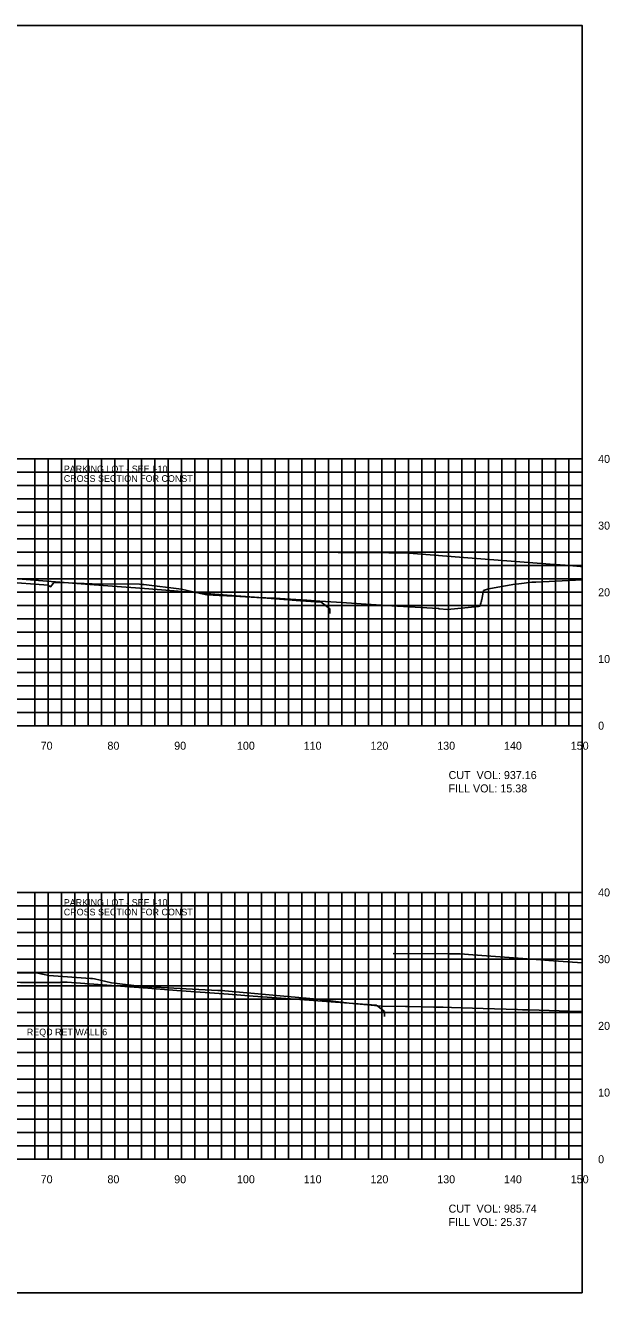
# Model space of a CAD drawing. Extents: x 1797682 to 1802785, y 249453 to 250269.
# Drawn here: x 1802697.6 to 1802785.1, y 250079.4 to 250269.4 of the extents above; entities that cross this region are included whole.
import ezdxf

# ---------------------------------------------------------------- set-up
doc = ezdxf.new("R2010")
doc.units = 0
for name, color, linetype in [('10', 7, 'Continuous'), ('3', 7, 'Continuous'), ('31', 7, 'Continuous'), ('60', 7, 'Continuous'), ('ANNO-TXT', 7, 'Continuous'), ('CL-CNST', 7, 'Continuous'), ('Level 62', 7, 'Continuous'), ('M-ROADS', 7, 'Continuous'), ('WEARING', 7, 'Continuous')]:
    doc.layers.add(name, color=color, linetype=linetype)

msp = doc.modelspace()

# ---------------------------------------------------------------- linework, layer by layer
msp.add_lwpolyline([(1802481, 250079.43), (1802781, 250079.43), (1802781, 250269.43), (1802481, 250269.43)], close=True)
at = {"layer": '60'}
for p, q in [((1802781, 250164.43), (1802781, 250204.43)), ((1802781.06, 250204.43), (1802781, 250204.43)), ((1802781.06, 250194.43), (1802781, 250194.43)), ((1802781.06, 250184.43), (1802781, 250184.43)), ((1802781.06, 250174.43), (1802781, 250174.43)), ((1802481, 250164.43), (1802781, 250164.43)), ((1802701, 250164.37), (1802701, 250164.43)), ((1802711, 250164.37), (1802711, 250164.43)), ((1802721, 250164.37), (1802721, 250164.43)), ((1802731, 250164.37), (1802731, 250164.43)), ((1802741, 250164.37), (1802741, 250164.43)), ((1802751, 250164.37), (1802751, 250164.43)), ((1802761, 250164.37), (1802761, 250164.43)), ((1802771, 250164.37), (1802771, 250164.43)), ((1802781, 250164.37), (1802781, 250164.43)), ((1802781.06, 250164.43), (1802781, 250164.43)), ((1802781, 250099.43), (1802781, 250139.43)), ((1802781.06, 250139.43), (1802781, 250139.43)), ((1802781.06, 250129.43), (1802781, 250129.43)), ((1802781.06, 250119.43), (1802781, 250119.43)), ((1802781.06, 250109.43), (1802781, 250109.43)), ((1802481, 250099.43), (1802781, 250099.43)), ((1802701, 250099.37), (1802701, 250099.43)), ((1802711, 250099.37), (1802711, 250099.43)), ((1802721, 250099.37), (1802721, 250099.43)), ((1802731, 250099.37), (1802731, 250099.43)), ((1802741, 250099.37), (1802741, 250099.43)), ((1802751, 250099.37), (1802751, 250099.43)), ((1802761, 250099.37), (1802761, 250099.43)), ((1802771, 250099.37), (1802771, 250099.43)), ((1802781, 250099.37), (1802781, 250099.43)), ((1802781.06, 250099.43), (1802781, 250099.43))]:
    msp.add_line(p, q, dxfattribs=at)
at = {"layer": 'CL-CNST'}
for points in [[(1802675.6, 250186.59), (1802684.84, 250186.52), (1802694.82, 250186.44), (1802694.86, 250186.48), (1802694.89, 250186.51), (1802695.31, 250186.51), (1802695.89, 250186.51), (1802700.81, 250186.12), (1802707.9, 250185.57), (1802715.46, 250184.99), (1802719.91, 250184.64), (1802727.84, 250184.02), (1802731.92, 250183.71), (1802738.8, 250183.17), (1802741.93, 250182.93), (1802742.32, 250182.63), (1802743.19, 250181.96), (1802743.19, 250181.45), (1802743.19, 250181.23)], [(1802691.8, 250125.97), (1802696.88, 250125.94), (1802702.8, 250125.92), (1802702.83, 250125.95), (1802702.87, 250125.98), (1802703.44, 250125.98), (1802703.88, 250125.98), (1802711.17, 250125.44), (1802715.95, 250125.08), (1802720.29, 250124.75), (1802728.02, 250124.18), (1802731.75, 250123.9), (1802740.1, 250123.28), (1802742.7, 250123.08), (1802750.16, 250122.53), (1802750.44, 250122.31), (1802751.42, 250121.56), (1802751.42, 250120.99), (1802751.42, 250120.83)]]:
    msp.add_lwpolyline(points, dxfattribs=at)
at = {"layer": 'Level 62'}
for p, q in [((1802481, 250204.43), (1802781, 250204.43)), ((1802699, 250164.43), (1802699, 250204.43)), ((1802701, 250164.43), (1802701, 250204.43)), ((1802703, 250164.43), (1802703, 250204.43)), ((1802705, 250164.43), (1802705, 250204.43)), ((1802707, 250164.43), (1802707, 250204.43)), ((1802709, 250164.43), (1802709, 250204.43)), ((1802711, 250164.43), (1802711, 250204.43)), ((1802713, 250164.43), (1802713, 250204.43)), ((1802715, 250164.43), (1802715, 250204.43)), ((1802717, 250164.43), (1802717, 250204.43)), ((1802719, 250164.43), (1802719, 250204.43)), ((1802721, 250164.43), (1802721, 250204.43)), ((1802723, 250164.43), (1802723, 250204.43)), ((1802725, 250164.43), (1802725, 250204.43)), ((1802727, 250164.43), (1802727, 250204.43)), ((1802729, 250164.43), (1802729, 250204.43)), ((1802731, 250164.43), (1802731, 250204.43)), ((1802733, 250164.43), (1802733, 250204.43)), ((1802735, 250164.43), (1802735, 250204.43)), ((1802737, 250164.43), (1802737, 250204.43)), ((1802739, 250164.43), (1802739, 250204.43)), ((1802741, 250164.43), (1802741, 250204.43)), ((1802743, 250164.43), (1802743, 250204.43)), ((1802745, 250164.43), (1802745, 250204.43)), ((1802747, 250164.43), (1802747, 250204.43)), ((1802749, 250164.43), (1802749, 250204.43)), ((1802751, 250164.43), (1802751, 250204.43)), ((1802753, 250164.43), (1802753, 250204.43)), ((1802755, 250164.43), (1802755, 250204.43)), ((1802757, 250164.43), (1802757, 250204.43)), ((1802759, 250164.43), (1802759, 250204.43)), ((1802761, 250164.43), (1802761, 250204.43)), ((1802763, 250164.43), (1802763, 250204.43)), ((1802765, 250164.43), (1802765, 250204.43)), ((1802767, 250164.43), (1802767, 250204.43)), ((1802769, 250164.43), (1802769, 250204.43)), ((1802771, 250164.43), (1802771, 250204.43)), ((1802773, 250164.43), (1802773, 250204.43)), ((1802775, 250164.43), (1802775, 250204.43)), ((1802777, 250164.43), (1802777, 250204.43)), ((1802779, 250164.43), (1802779, 250204.43)), ((1802781, 250164.43), (1802781, 250204.43)), ((1802481, 250202.43), (1802781, 250202.43)), ((1802481, 250200.43), (1802781, 250200.43)), ((1802481, 250198.43), (1802781, 250198.43)), ((1802481, 250196.43), (1802781, 250196.43)), ((1802481, 250194.43), (1802781, 250194.43)), ((1802481, 250192.43), (1802781, 250192.43)), ((1802481, 250190.43), (1802781, 250190.43)), ((1802481, 250188.43), (1802781, 250188.43)), ((1802481, 250186.43), (1802781, 250186.43)), ((1802481, 250184.43), (1802781, 250184.43)), ((1802481, 250182.43), (1802781, 250182.43)), ((1802481, 250180.43), (1802781, 250180.43)), ((1802481, 250178.43), (1802781, 250178.43)), ((1802481, 250176.43), (1802781, 250176.43)), ((1802481, 250174.43), (1802781, 250174.43)), ((1802481, 250172.43), (1802781, 250172.43)), ((1802481, 250170.43), (1802781, 250170.43)), ((1802481, 250168.43), (1802781, 250168.43)), ((1802481, 250166.43), (1802781, 250166.43)), ((1802481, 250164.43), (1802781, 250164.43)), ((1802481, 250139.43), (1802781, 250139.43)), ((1802699, 250099.43), (1802699, 250139.43)), ((1802701, 250099.43), (1802701, 250139.43)), ((1802703, 250099.43), (1802703, 250139.43)), ((1802705, 250099.43), (1802705, 250139.43)), ((1802707, 250099.43), (1802707, 250139.43)), ((1802709, 250099.43), (1802709, 250139.43)), ((1802711, 250099.43), (1802711, 250139.43)), ((1802713, 250099.43), (1802713, 250139.43)), ((1802715, 250099.43), (1802715, 250139.43)), ((1802717, 250099.43), (1802717, 250139.43)), ((1802719, 250099.43), (1802719, 250139.43)), ((1802721, 250099.43), (1802721, 250139.43)), ((1802723, 250099.43), (1802723, 250139.43)), ((1802725, 250099.43), (1802725, 250139.43)), ((1802727, 250099.43), (1802727, 250139.43)), ((1802729, 250099.43), (1802729, 250139.43)), ((1802731, 250099.43), (1802731, 250139.43)), ((1802733, 250099.43), (1802733, 250139.43)), ((1802735, 250099.43), (1802735, 250139.43)), ((1802737, 250099.43), (1802737, 250139.43)), ((1802739, 250099.43), (1802739, 250139.43)), ((1802741, 250099.43), (1802741, 250139.43)), ((1802743, 250099.43), (1802743, 250139.43)), ((1802745, 250099.43), (1802745, 250139.43)), ((1802747, 250099.43), (1802747, 250139.43)), ((1802749, 250099.43), (1802749, 250139.43)), ((1802751, 250099.43), (1802751, 250139.43)), ((1802753, 250099.43), (1802753, 250139.43)), ((1802755, 250099.43), (1802755, 250139.43)), ((1802757, 250099.43), (1802757, 250139.43)), ((1802759, 250099.43), (1802759, 250139.43)), ((1802761, 250099.43), (1802761, 250139.43)), ((1802763, 250099.43), (1802763, 250139.43)), ((1802765, 250099.43), (1802765, 250139.43)), ((1802767, 250099.43), (1802767, 250139.43)), ((1802769, 250099.43), (1802769, 250139.43)), ((1802771, 250099.43), (1802771, 250139.43)), ((1802773, 250099.43), (1802773, 250139.43)), ((1802775, 250099.43), (1802775, 250139.43)), ((1802777, 250099.43), (1802777, 250139.43)), ((1802779, 250099.43), (1802779, 250139.43)), ((1802781, 250099.43), (1802781, 250139.43)), ((1802481, 250137.43), (1802781, 250137.43)), ((1802481, 250135.43), (1802781, 250135.43)), ((1802481, 250133.43), (1802781, 250133.43)), ((1802481, 250131.43), (1802781, 250131.43)), ((1802481, 250129.43), (1802781, 250129.43)), ((1802481, 250127.43), (1802781, 250127.43)), ((1802481, 250125.43), (1802781, 250125.43)), ((1802481, 250123.43), (1802781, 250123.43)), ((1802481, 250121.43), (1802781, 250121.43)), ((1802481, 250119.43), (1802781, 250119.43)), ((1802481, 250117.43), (1802781, 250117.43)), ((1802481, 250115.43), (1802781, 250115.43)), ((1802481, 250113.43), (1802781, 250113.43)), ((1802481, 250111.43), (1802781, 250111.43)), ((1802481, 250109.43), (1802781, 250109.43)), ((1802481, 250107.43), (1802781, 250107.43)), ((1802481, 250105.43), (1802781, 250105.43)), ((1802481, 250103.43), (1802781, 250103.43)), ((1802481, 250101.43), (1802781, 250101.43)), ((1802481, 250099.43), (1802781, 250099.43))]:
    msp.add_line(p, q, dxfattribs=at)
at = {"layer": 'M-ROADS'}
for points in [[(1802694.38, 250185.98), (1802701.04, 250185.49), (1802701.12, 250185.42), (1802701.2, 250185.35), (1802701.38, 250185.27), (1802701.76, 250185.77), (1802701.84, 250185.86), (1802702.86, 250185.91), (1802707.63, 250185.72), (1802714.7, 250185.63), (1802715.17, 250185.6), (1802715.35, 250185.58), (1802720.97, 250184.88), (1802721.83, 250184.69), (1802723.65, 250184.29), (1802723.82, 250184.27), (1802724.8, 250184.04), (1802726.63, 250183.94), (1802728.89, 250183.83), (1802732.27, 250183.66), (1802734.99, 250183.54), (1802738.13, 250183.34), (1802739.75, 250183.23), (1802739.77, 250183.23), (1802741.69, 250183.11), (1802744.21, 250182.94), (1802746.47, 250182.8), (1802751.61, 250182.47), (1802759.51, 250181.98), (1802759.58, 250181.97), (1802760.84, 250181.85), (1802765.47, 250182.32), (1802765.72, 250182.37), (1802765.79, 250182.63), (1802765.83, 250182.79), (1802765.88, 250182.99), (1802765.91, 250183.1), (1802765.95, 250183.25), (1802765.97, 250183.33), (1802765.99, 250183.44), (1802766.01, 250183.5), (1802766.03, 250183.58), (1802766.04, 250183.63), (1802766.25, 250184.68), (1802766.83, 250184.9), (1802767.29, 250184.99), (1802770.94, 250185.67), (1802771.52, 250185.7), (1802773.45, 250185.93), (1802773.5, 250185.94), (1802774.06, 250185.97), (1802781, 250186.32)], [(1802695.46, 250127.33), (1802698.6, 250127.4), (1802699.04, 250127.38), (1802699.23, 250127.37), (1802701.13, 250126.98), (1802707.37, 250126.52), (1802707.64, 250126.51), (1802707.95, 250126.5), (1802710.52, 250125.88), (1802715.08, 250125.34), (1802726.44, 250124.73), (1802726.44, 250124.73), (1802726.46, 250124.73), (1802726.47, 250124.73), (1802726.82, 250124.73), (1802727.03, 250124.73), (1802727.15, 250124.74), (1802727.47, 250124.7), (1802727.49, 250124.7), (1802741.3, 250123.41), (1802746.11, 250122.82), (1802746.64, 250122.77), (1802749.42, 250122.53), (1802750.88, 250122.4), (1802754.55, 250122.32), (1802754.97, 250122.31), (1802758.78, 250122.24), (1802760.19, 250122.21), (1802761.42, 250122.19), (1802766.18, 250122.02), (1802771.31, 250121.86), (1802772.06, 250121.84), (1802772.13, 250121.83), (1802772.28, 250121.83), (1802773.06, 250121.81), (1802777.58, 250121.66), (1802780.21, 250121.58), (1802781, 250121.56)]]:
    msp.add_lwpolyline(points, dxfattribs=at)
at = {"layer": 'WEARING'}
for points in [[(1802744.44, 250190.41), (1802752.03, 250190.35), (1802754.45, 250190.33), (1802763.88, 250189.61), (1802766.46, 250189.4), (1802776.23, 250188.65), (1802778.48, 250188.48), (1802780.77, 250188.3), (1802781, 250188.28)], [(1802752.68, 250130.26), (1802761.02, 250130.22), (1802762.74, 250130.21), (1802764.62, 250130.07), (1802774.81, 250129.32), (1802776.04, 250129.23), (1802781, 250128.86)]]:
    msp.add_lwpolyline(points, dxfattribs=at)

# ---------------------------------------------------------------- texts
at = {"layer": '10'}
for s, p in [('70', (1802699.9, 250160.83)), ('80', (1802709.9, 250160.83)), ('90', (1802719.9, 250160.83)), ('100', (1802729.3, 250160.83)), ('110', (1802739.3, 250160.83)), ('120', (1802749.3, 250160.83)), ('130', (1802759.3, 250160.83)), ('140', (1802769.3, 250160.83)), ('150', (1802779.3, 250160.83)), ('70', (1802699.9, 250095.83)), ('80', (1802709.9, 250095.83)), ('90', (1802719.9, 250095.83)), ('100', (1802729.3, 250095.83)), ('110', (1802739.3, 250095.83)), ('120', (1802749.3, 250095.83)), ('130', (1802759.3, 250095.83)), ('140', (1802769.3, 250095.83)), ('150', (1802779.3, 250095.83))]:
    msp.add_text(s, height=1.2, dxfattribs=at).set_placement(p)
at = {"layer": '3'}
for s, p in [('PARKING LOT - SEE I-10', (1802703.36, 250202.43)), ('CROSS SECTION FOR CONST ', (1802703.36, 250200.99)), ('CROSS SECTION FOR CONST ', (1802703.36, 250135.99)), ('PARKING LOT - SEE I-10', (1802703.36, 250137.43)), ('REQD RET WALL 6', (1802697.82, 250118.01))]:
    msp.add_text(s, height=1, dxfattribs=at).set_placement(p)
at = {"layer": '31'}
for s, p in [('40', (1802783.4, 250203.83)), ('30', (1802783.4, 250193.83)), ('20', (1802783.4, 250183.83)), ('10', (1802783.4, 250173.83)), ('0', (1802783.4, 250163.83)), ('40', (1802783.4, 250138.83)), ('30', (1802783.4, 250128.83)), ('20', (1802783.4, 250118.83)), ('10', (1802783.4, 250108.83)), ('0', (1802783.4, 250098.83))]:
    msp.add_text(s, height=1.2, dxfattribs=at).set_placement(p)
at = {"layer": 'ANNO-TXT'}
for s, p in [('CUT  VOL: 937.16', (1802761, 250156.43)), ('FILL VOL: 15.38', (1802761, 250154.43)), ('CUT  VOL: 985.74', (1802761, 250091.43)), ('FILL VOL: 25.37', (1802761, 250089.43))]:
    msp.add_text(s, height=1.2, dxfattribs=at).set_placement(p)

doc.saveas('drawing.dxf')
